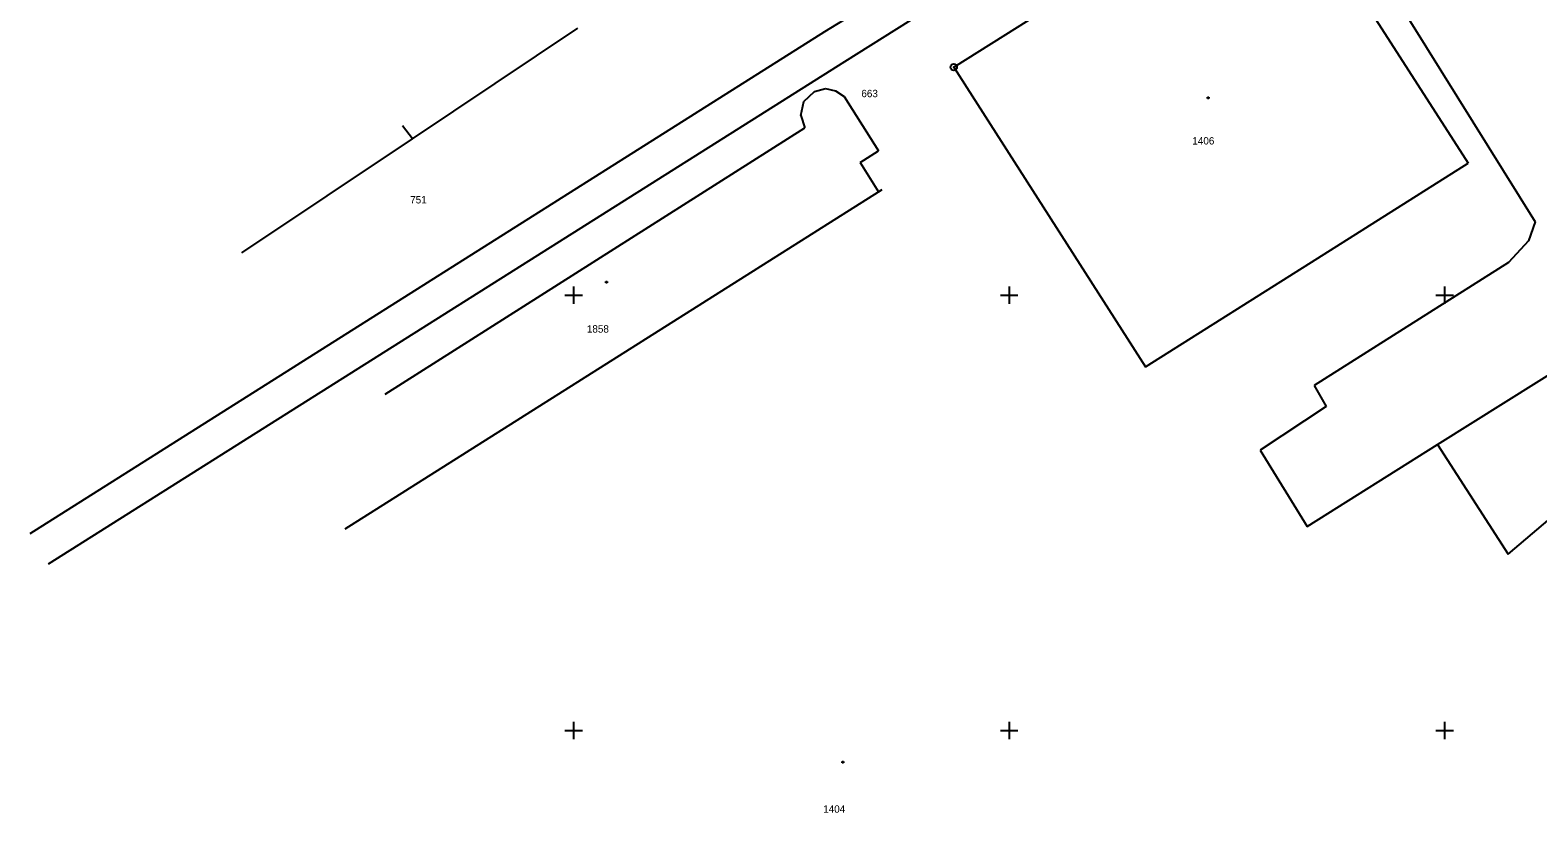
# Model space of a CAD drawing. Extents: x -492379 to -491966, y -1126153 to -1125860.
# Drawn here: x -492337.4 to -492233.6, y -1126145.7 to -1126091.7 of the extents above; entities that cross this region are included whole.
import ezdxf

# ---------------------------------------------------------------- set-up
doc = ezdxf.new("R2010")
doc.units = 0
doc.layers.add('katastrální mapa', color=7, linetype='Continuous')
doc.layers.add('síť', color=7, linetype='Continuous')

msp = doc.modelspace()

# ---------------------------------------------------------------- linework, layer by layer
at = {"layer": 'katastrální mapa'}
for p, q in [((-492282.7, -1126091.84), (-492226.15, -1126056.69)), ((-492250.32, -1126078.33), (-492233.77, -1126104.94)), ((-492273.82, -1126094.29), (-492251.59, -1126080.29)), ((-492251.59, -1126080.29), (-492238.38, -1126100.91)), ((-492281.31, -1126093.89), (-492264.32, -1126083.19)), ((-492337.44, -1126126.42), (-492282.7, -1126091.84)), ((-492311.11, -1126099.22), (-492299.71, -1126091.6)), ((-492336.18, -1126128.5), (-492281.31, -1126093.89)), ((-492273.82, -1126094.29), (-492260.61, -1126114.93)), ((-492284.14, -1126096.65), (-492283.41, -1126095.96)), ((-492283.41, -1126095.96), (-492282.65, -1126095.77)), ((-492282.65, -1126095.77), (-492281.97, -1126095.91)), ((-492281.97, -1126095.91), (-492281.37, -1126096.31)), ((-492284.35, -1126097.62), (-492284.14, -1126096.65)), ((-492281.37, -1126096.31), (-492278.99, -1126100.06)), ((-492256.33, -1126096.36), (-492256.24, -1126096.36)), ((-492256.33, -1126096.45), (-492256.33, -1126096.36)), ((-492256.24, -1126096.45), (-492256.33, -1126096.45)), ((-492256.24, -1126096.36), (-492256.24, -1126096.45)), ((-492284.35, -1126097.62), (-492284.07, -1126098.48)), ((-492322.86, -1126107.09), (-492311.11, -1126099.22)), ((-492312.99, -1126116.83), (-492284.07, -1126098.48)), ((-492311.11, -1126099.22), (-492311.8, -1126098.34)), ((-492280.26, -1126100.87), (-492278.99, -1126100.06)), ((-492280.26, -1126100.87), (-492278.99, -1126102.88)), ((-492248.74, -1126107.44), (-492238.38, -1126100.91)), ((-492240.49, -1126120.29), (-492208.8, -1126100.37)), ((-492315.74, -1126126.1), (-492278.99, -1126102.88)), ((-492278.99, -1126102.88), (-492278.75, -1126102.73)), ((-492233.77, -1126104.94), (-492234.22, -1126106.26)), ((-492234.22, -1126106.26), (-492235.59, -1126107.76)), ((-492260.61, -1126114.93), (-492248.74, -1126107.44)), ((-492235.59, -1126107.76), (-492248.99, -1126116.23)), ((-492297.78, -1126109.05), (-492297.69, -1126109.05)), ((-492297.78, -1126109.14), (-492297.78, -1126109.05)), ((-492297.69, -1126109.14), (-492297.78, -1126109.14)), ((-492297.69, -1126109.05), (-492297.69, -1126109.14)), ((-492248.99, -1126116.23), (-492248.16, -1126117.68)), ((-492248.16, -1126117.68), (-492252.71, -1126120.67)), ((-492235.63, -1126127.85), (-492223.65, -1126117.64)), ((-492252.71, -1126120.67), (-492249.46, -1126125.93)), ((-492249.46, -1126125.93), (-492240.49, -1126120.29)), ((-492240.49, -1126120.29), (-492235.63, -1126127.85)), ((-492281.5, -1126142.13), (-492281.41, -1126142.13)), ((-492281.5, -1126142.22), (-492281.5, -1126142.13)), ((-492281.41, -1126142.22), (-492281.5, -1126142.22)), ((-492281.41, -1126142.13), (-492281.41, -1126142.22))]:
    msp.add_line(p, q, dxfattribs=at)
for radius in [0.225, 0.003]:
    msp.add_circle((-492273.82, -1126094.29), radius, dxfattribs=at)
at = {"layer": 'síť'}
for p, q in [((-492300, -1126109.4), (-492300, -1126110.6)), ((-492270, -1126109.4), (-492270, -1126110.6)), ((-492240, -1126109.4), (-492240, -1126110.6)), ((-492300.6, -1126110), (-492299.4, -1126110)), ((-492270.6, -1126110), (-492269.4, -1126110)), ((-492240.6, -1126110), (-492239.4, -1126110)), ((-492300, -1126139.4), (-492300, -1126140.6)), ((-492270, -1126139.4), (-492270, -1126140.6)), ((-492240, -1126139.4), (-492240, -1126140.6)), ((-492300.6, -1126140), (-492299.4, -1126140)), ((-492270.6, -1126140), (-492269.4, -1126140)), ((-492240.6, -1126140), (-492239.4, -1126140))]:
    msp.add_line(p, q, dxfattribs=at)

# ---------------------------------------------------------------- texts
at = {"layer": 'katastrální mapa'}
for s, p in [('663', (-492280.18, -1126096.36)), ('1406', (-492257.38, -1126099.62)), ('751', (-492311.26, -1126103.68)), ('1858', (-492299.09, -1126112.58)), ('1404', (-492282.81, -1126145.66))]:
    msp.add_text(s, height=0.51, dxfattribs=at).set_placement(p)

doc.saveas('drawing.dxf')
